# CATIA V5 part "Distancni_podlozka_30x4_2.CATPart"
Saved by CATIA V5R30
Part number: Dosedaci_podlozka_30x4_2
Definition: E 1500_30x4_1
Nomenclature: E 1500_30x4_1
Source: Unknown
Description: PART--DESC
Bounding box of the stored display mesh (mm): x -219 to -189, y 75 to 105, z -224 to -220
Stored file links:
  E:\Bakalarka\Model\Forma_v7\Distancni_podlozka_30x4_2.CATPart
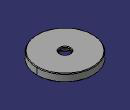
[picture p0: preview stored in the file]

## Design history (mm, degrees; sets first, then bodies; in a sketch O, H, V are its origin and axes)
Body1 "MANIFOLD_SOLID_BREP #4074" (main body)
  Solid1: solid without history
